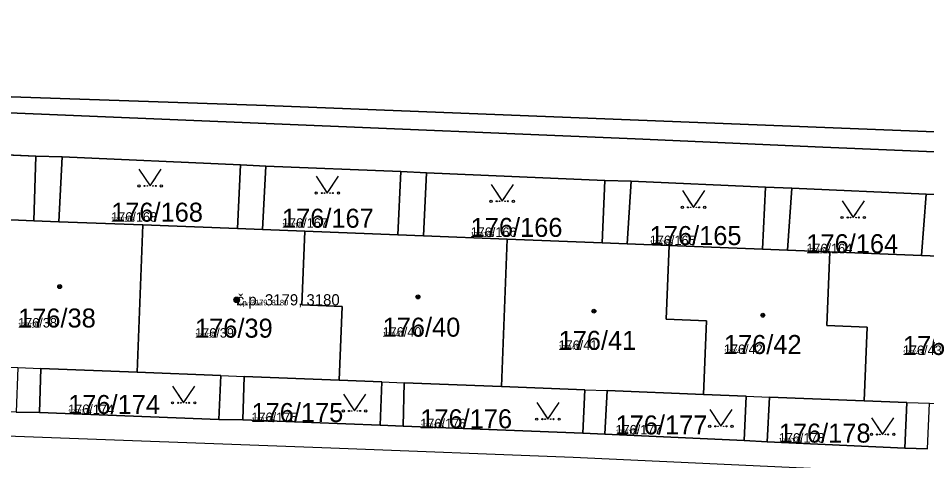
# Model space of a CAD drawing. Extents: x -759873 to -758487, y -975024 to -973516.
# Drawn here: x -759380.2 to -759298.9, y -974864.9 to -974825.3 of the extents above; entities that cross this region are included whole.
import ezdxf

# ---------------------------------------------------------------- set-up
doc = ezdxf.new("R2010")
doc.units = 0
for name, color, linetype in [('KAT_02_hranice parcel', 7, 'Continuous'), ('KAT_03_1000_st čísla parcelní', 7, 'Continuous'), ('KAT_03_1000_čísla parcelní', 7, 'Continuous'), ('KAT_03_1000_čísla popisná', 7, 'Continuous'), ('KAT_03_250_st čísla parcelní', 7, 'Continuous'), ('KAT_03_250_čísla parcelní', 7, 'Continuous'), ('KAT_03_250_čísla popisná', 7, 'Continuous'), ('KAT_03_500_st čísla parcelní', 7, 'Continuous'), ('KAT_03_500_čísla parcelní', 7, 'Continuous'), ('KAT_03_500_čísla popisná', 7, 'Continuous'), ('KAT_04_vnitřní kresba', 7, 'Continuous'), ('KAT_05_1000_značky kultur', 7, 'Continuous'), ('KAT_05_250_značky kultur', 7, 'Continuous'), ('KAT_05_500_značky kultur', 7, 'Continuous'), ('KAT_07_1000_značky budov', 7, 'Continuous'), ('KAT_07_250_značky budov', 7, 'Continuous'), ('KAT_07_500_značky budov', 7, 'Continuous'), ('KAT_14_plocha_budovy', 7, 'Continuous'), ('KAT_14_plocha_pozemek', 7, 'Continuous')]:
    doc.layers.add(name, color=color, linetype=linetype)

msp = doc.modelspace()

# ---------------------------------------------------------------- linework, layer by layer
at = {"layer": 'KAT_02_hranice parcel'}
for p, q in [((-759390.6, -974837.16), (-759378.65, -974837.7)), ((-759376.31, -974837.75), (-759378.65, -974837.7)), ((-759376.31, -974837.75), (-759360.35, -974838.46)), ((-759358.06, -974838.57), (-759360.35, -974838.46)), ((-759358.06, -974838.57), (-759345.99, -974839.06)), ((-759343.69, -974839.17), (-759345.99, -974839.06)), ((-759343.69, -974839.17), (-759327.72, -974839.85)), ((-759325.36, -974839.92), (-759327.72, -974839.85)), ((-759325.36, -974839.92), (-759313.34, -974840.46)), ((-759311, -974840.55), (-759313.34, -974840.46)), ((-759311, -974840.55), (-759298.96, -974841.08)), ((-759296.85, -974841.17), (-759298.96, -974841.08)), ((-759369.6, -974857.02), (-759369.08, -974843.84)), ((-759336.99, -974858.3), (-759336.48, -974845.12)), ((-759380.41, -974860.6), (-759378.32, -974860.64)), ((-759378.32, -974860.64), (-759362.27, -974861.24)), ((-759362.27, -974861.24), (-759360.14, -974861.28)), ((-759360.14, -974861.28), (-759347.83, -974861.77)), ((-759347.83, -974861.77), (-759345.79, -974861.85)), ((-759345.79, -974861.85), (-759329.71, -974862.47)), ((-759329.71, -974862.47), (-759327.72, -974862.56)), ((-759327.72, -974862.56), (-759315.26, -974863.12)), ((-759315.26, -974863.12), (-759313.19, -974863.24)), ((-759313.19, -974863.24), (-759300.86, -974863.82)), ((-759300.86, -974863.82), (-759298.85, -974863.88))]:
    msp.add_line(p, q, dxfattribs=at)
for points in [[(-759382.67, -974832.32), (-759358.04, -974833.14), (-759286.08, -974836), (-759287.93, -974822.96), (-759288.84, -974816.61), (-759289.72, -974807.13), (-759291.76, -974802.52), (-759298.13, -974787.72), (-759322.87, -974786.95)], [(-759281.55, -974837.72), (-759288.97, -974837.7), (-759308.21, -974836.87), (-759325.02, -974836.15), (-759358.04, -974834.77), (-759390.43, -974833.42), (-759411.31, -974832.59), (-759418.48, -974833.88), (-759427.06, -974838.9), (-759442.22, -974854.65)], [(-759378.65, -974837.7), (-759378.84, -974843.46), (-759387.18, -974843.13)], [(-759369.08, -974843.84), (-759376.59, -974843.55), (-759376.31, -974837.75)], [(-759360.35, -974838.46), (-759360.62, -974844.17), (-759369.08, -974843.84)], [(-759354.58, -974844.41), (-759358.36, -974844.26), (-759358.06, -974838.57)], [(-759345.99, -974839.06), (-759346.25, -974844.74), (-759354.58, -974844.41)], [(-759336.48, -974845.12), (-759343.97, -974844.83), (-759343.69, -974839.17)], [(-759327.72, -974839.85), (-759327.98, -974845.45), (-759336.48, -974845.12)], [(-759321.97, -974845.68), (-759325.73, -974845.54), (-759325.36, -974839.92)], [(-759313.34, -974840.46), (-759313.6, -974846.01), (-759321.97, -974845.68)], [(-759307.59, -974846.25), (-759311.37, -974846.1), (-759311, -974840.55)], [(-759298.96, -974841.08), (-759299.38, -974846.57), (-759307.59, -974846.25)], [(-759351.5, -974857.73), (-759351.24, -974851.14), (-759354.84, -974850.99), (-759354.58, -974844.41)], [(-759318.89, -974859.01), (-759318.63, -974852.41), (-759322.23, -974852.27), (-759321.97, -974845.68)], [(-759304.51, -974859.57), (-759304.25, -974852.98), (-759307.85, -974852.84), (-759307.59, -974846.25)], [(-759378.32, -974860.64), (-759378.22, -974856.68), (-759369.6, -974857.02)], [(-759369.6, -974857.02), (-759362.1, -974857.31), (-759362.27, -974861.24)], [(-759360.14, -974861.28), (-759360.02, -974857.4), (-759351.5, -974857.73)], [(-759351.5, -974857.73), (-759347.69, -974857.88), (-759347.83, -974861.77)], [(-759345.79, -974861.85), (-759345.68, -974857.96), (-759336.99, -974858.3)], [(-759336.99, -974858.3), (-759329.52, -974858.59), (-759329.71, -974862.47)], [(-759327.72, -974862.56), (-759327.52, -974858.67), (-759318.89, -974859.01)], [(-759318.89, -974859.01), (-759315.08, -974859.16), (-759315.26, -974863.12)], [(-759313.19, -974863.24), (-759313, -974859.24), (-759304.51, -974859.57)], [(-759304.51, -974859.57), (-759300.7, -974859.72), (-759300.86, -974863.82)]]:
    msp.add_lwpolyline(points, dxfattribs=at)
at = {"layer": 'KAT_03_1000_čísla popisná'}
msp.add_circle((-759360.68, -974850.54), 0.25, dxfattribs=at)
at = {"layer": 'KAT_03_250_čísla popisná'}
msp.add_circle((-759360.68, -974850.54), 0.0625, dxfattribs=at)
at = {"layer": 'KAT_03_500_čísla popisná'}
msp.add_circle((-759360.68, -974850.54), 0.125, dxfattribs=at)
at = {"layer": 'KAT_04_vnitřní kresba'}
for p, q in [((-759378.84, -974843.46), (-759376.59, -974843.55)), ((-759360.62, -974844.17), (-759358.36, -974844.26)), ((-759346.25, -974844.74), (-759343.97, -974844.83)), ((-759327.98, -974845.45), (-759325.73, -974845.54)), ((-759313.6, -974846.01), (-759311.37, -974846.1)), ((-759299.38, -974846.57), (-759297.02, -974846.66)), ((-759380.28, -974856.6), (-759378.22, -974856.68)), ((-759362.1, -974857.31), (-759360.02, -974857.4)), ((-759347.69, -974857.88), (-759345.68, -974857.96)), ((-759329.52, -974858.59), (-759327.52, -974858.67)), ((-759315.08, -974859.16), (-759313, -974859.24)), ((-759300.7, -974859.72), (-759298.66, -974859.8)), ((-759382.57, -974862.68), (-759352.26, -974863.8)), ((-759352.26, -974863.8), (-759330.55, -974864.62)), ((-759330.55, -974864.62), (-759305.43, -974865.78))]:
    msp.add_line(p, q, dxfattribs=at)
at = {"layer": 'KAT_05_1000_značky kultur'}
for points in [[(-759369.43, -974838.849), (-759368.43, -974840.35), (-759367.43, -974838.849)], [(-759353.57, -974839.489), (-759352.57, -974840.99), (-759351.57, -974839.489)], [(-759337.91, -974840.219), (-759336.91, -974841.72), (-759335.91, -974840.219)], [(-759320.79, -974840.769), (-759319.79, -974842.27), (-759318.79, -974840.769)], [(-759306.49, -974841.679), (-759305.49, -974843.18), (-759304.49, -974841.679)], [(-759366.43, -974858.259), (-759365.43, -974859.76), (-759364.43, -974858.259)], [(-759351.13, -974858.989), (-759350.13, -974860.49), (-759349.13, -974858.989)], [(-759333.82, -974859.719), (-759332.82, -974861.22), (-759331.82, -974859.719)], [(-759318.34, -974860.359), (-759317.34, -974861.86), (-759316.34, -974860.359)], [(-759303.86, -974861.089), (-759302.86, -974862.59), (-759301.86, -974861.089)]]:
    msp.add_lwpolyline(points, dxfattribs=at)
for centre in [(-759369.43, -974840.349), (-759367.43, -974840.349), (-759353.57, -974840.989), (-759351.57, -974840.989), (-759337.91, -974841.719), (-759335.91, -974841.719), (-759320.79, -974842.269), (-759318.79, -974842.269), (-759306.49, -974843.179), (-759304.49, -974843.179), (-759366.43, -974859.759), (-759364.43, -974859.759), (-759351.13, -974860.489), (-759349.13, -974860.489), (-759333.82, -974861.219), (-759331.82, -974861.219), (-759318.34, -974861.859), (-759316.34, -974861.859), (-759303.86, -974862.589), (-759301.86, -974862.589)]:
    msp.add_circle(centre, 0.1, dxfattribs=at)
at = {"layer": 'KAT_05_250_značky kultur'}
for points in [[(-759368.68, -974839.975), (-759368.43, -974840.35), (-759368.18, -974839.975)], [(-759352.82, -974840.615), (-759352.57, -974840.99), (-759352.32, -974840.615)], [(-759337.16, -974841.345), (-759336.91, -974841.72), (-759336.66, -974841.345)], [(-759320.04, -974841.895), (-759319.79, -974842.27), (-759319.54, -974841.895)], [(-759305.74, -974842.805), (-759305.49, -974843.18), (-759305.24, -974842.805)], [(-759365.68, -974859.385), (-759365.43, -974859.76), (-759365.18, -974859.385)], [(-759350.38, -974860.115), (-759350.13, -974860.49), (-759349.88, -974860.115)], [(-759333.07, -974860.845), (-759332.82, -974861.22), (-759332.57, -974860.845)], [(-759317.59, -974861.485), (-759317.34, -974861.86), (-759317.09, -974861.485)], [(-759303.11, -974862.215), (-759302.86, -974862.59), (-759302.61, -974862.215)]]:
    msp.add_lwpolyline(points, dxfattribs=at)
for centre in [(-759368.68, -974840.35), (-759368.18, -974840.35), (-759352.82, -974840.99), (-759352.32, -974840.99), (-759337.16, -974841.72), (-759336.66, -974841.72), (-759320.04, -974842.27), (-759319.54, -974842.27), (-759305.74, -974843.18), (-759305.24, -974843.18), (-759365.68, -974859.76), (-759365.18, -974859.76), (-759350.38, -974860.49), (-759349.88, -974860.49), (-759333.07, -974861.22), (-759332.57, -974861.22), (-759317.59, -974861.86), (-759317.09, -974861.86), (-759303.11, -974862.59), (-759302.61, -974862.59)]:
    msp.add_circle(centre, 0.025, dxfattribs=at)
at = {"layer": 'KAT_05_500_značky kultur'}
for points in [[(-759368.93, -974839.6), (-759368.43, -974840.35), (-759367.93, -974839.6)], [(-759353.07, -974840.24), (-759352.57, -974840.99), (-759352.07, -974840.24)], [(-759337.41, -974840.97), (-759336.91, -974841.72), (-759336.41, -974840.97)], [(-759320.29, -974841.52), (-759319.79, -974842.27), (-759319.29, -974841.52)], [(-759305.99, -974842.429), (-759305.49, -974843.18), (-759304.99, -974842.429)], [(-759365.93, -974859.01), (-759365.43, -974859.76), (-759364.93, -974859.01)], [(-759350.63, -974859.74), (-759350.13, -974860.49), (-759349.63, -974859.74)], [(-759333.32, -974860.47), (-759332.82, -974861.22), (-759332.32, -974860.47)], [(-759317.84, -974861.11), (-759317.34, -974861.86), (-759316.84, -974861.11)], [(-759303.36, -974861.84), (-759302.86, -974862.59), (-759302.36, -974861.84)]]:
    msp.add_lwpolyline(points, dxfattribs=at)
for centre in [(-759368.93, -974840.35), (-759367.93, -974840.35), (-759353.07, -974840.99), (-759352.07, -974840.99), (-759337.41, -974841.72), (-759336.41, -974841.72), (-759320.29, -974842.27), (-759319.29, -974842.27), (-759305.99, -974843.18), (-759304.99, -974843.18), (-759365.93, -974859.76), (-759364.93, -974859.76), (-759350.63, -974860.49), (-759349.63, -974860.49), (-759333.32, -974861.22), (-759332.32, -974861.22), (-759317.84, -974861.86), (-759316.84, -974861.86), (-759303.36, -974862.59), (-759302.36, -974862.59)]:
    msp.add_circle(centre, 0.05, dxfattribs=at)
at = {"layer": 'KAT_07_1000_značky budov'}
for centre in [(-759376.527, -974849.359), (-759360.687, -974850.539), (-759344.457, -974850.279), (-759328.707, -974851.559), (-759313.587, -974851.919)]:
    msp.add_circle(centre, 0.175, dxfattribs=at)
at = {"layer": 'KAT_07_250_značky budov'}
for centre in [(-759376.522, -974849.36), (-759360.682, -974850.54), (-759344.452, -974850.28), (-759328.702, -974851.56), (-759313.582, -974851.92)]:
    msp.add_circle(centre, 0.0437, dxfattribs=at)
at = {"layer": 'KAT_07_500_značky budov'}
for centre in [(-759376.523, -974849.36), (-759360.683, -974850.54), (-759344.453, -974850.28), (-759328.703, -974851.56), (-759313.583, -974851.92)]:
    msp.add_circle(centre, 0.0875, dxfattribs=at)
at = {"layer": 'KAT_14_plocha_budovy'}
for points in [[(-759369.6, -974857.02), (-759369.08, -974843.84), (-759376.59, -974843.55), (-759378.84, -974843.46), (-759387.18, -974843.13), (-759390.57, -974843), (-759393.24, -974842.9), (-759401.56, -974842.57), (-759405.36, -974842.42), (-759407.59, -974842.34), (-759416.17, -974842), (-759416.68, -974855.18), (-759409.09, -974855.48), (-759407.03, -974855.56), (-759398.48, -974855.89), (-759394.62, -974856.04), (-759392.65, -974856.12), (-759384.11, -974856.45), (-759380.28, -974856.6), (-759378.22, -974856.68)], [(-759369.6, -974857.02), (-759362.1, -974857.31), (-759360.02, -974857.4), (-759351.5, -974857.73), (-759347.69, -974857.88), (-759345.68, -974857.96), (-759336.99, -974858.3), (-759336.48, -974845.12), (-759343.97, -974844.83), (-759346.25, -974844.74), (-759354.58, -974844.41), (-759358.36, -974844.26), (-759360.62, -974844.17), (-759369.08, -974843.84)], [(-759304.51, -974859.57), (-759300.7, -974859.72), (-759298.66, -974859.8), (-759289.9, -974860.14), (-759289.38, -974846.96), (-759297.02, -974846.66), (-759299.38, -974846.57), (-759307.59, -974846.25), (-759311.37, -974846.1), (-759313.6, -974846.01), (-759321.97, -974845.68), (-759325.73, -974845.54), (-759327.98, -974845.45), (-759336.48, -974845.12), (-759336.99, -974858.3), (-759329.52, -974858.59), (-759327.52, -974858.67), (-759318.89, -974859.01), (-759315.08, -974859.16), (-759313, -974859.24)]]:
    msp.add_lwpolyline(points, close=True, dxfattribs=at)
at = {"layer": 'KAT_14_plocha_pozemek'}
for points in [[(-759286.08, -974836), (-759358.04, -974833.14), (-759382.67, -974832.32), (-759413.9, -974831.28), (-759416.69, -974831.27), (-759419.67, -974831.59), (-759422.46, -974832.5), (-759424.85, -974834.26), (-759443.37, -974853.62), (-759442.22, -974854.65), (-759427.06, -974838.9), (-759418.48, -974833.88), (-759411.31, -974832.59), (-759390.43, -974833.42), (-759358.04, -974834.77), (-759325.02, -974836.15), (-759308.21, -974836.87), (-759288.97, -974837.7)], [(-759382.67, -974832.32), (-759358.04, -974833.14), (-759286.08, -974836)], [(-759288.97, -974837.7), (-759308.21, -974836.87), (-759325.02, -974836.15), (-759358.04, -974834.77), (-759390.43, -974833.42)], [(-759390.6, -974837.16), (-759378.65, -974837.7), (-759376.31, -974837.75), (-759360.35, -974838.46), (-759358.06, -974838.57), (-759345.99, -974839.06), (-759343.69, -974839.17), (-759327.72, -974839.85), (-759325.36, -974839.92), (-759313.34, -974840.46), (-759311, -974840.55), (-759298.96, -974841.08), (-759296.85, -974841.17)], [(-759378.32, -974860.64), (-759380.41, -974860.6), (-759392.56, -974860.11), (-759394.77, -974860.08), (-759407.08, -974859.58), (-759409.14, -974859.51), (-759420.83, -974858.95), (-759422.15, -974858.9), (-759440.79, -974858.2), (-759441.93, -974860.34), (-759434.47, -974860.67), (-759434.72, -974865.02)], [(-759298.85, -974863.88), (-759300.86, -974863.82), (-759313.19, -974863.24), (-759315.26, -974863.12), (-759327.72, -974862.56), (-759329.71, -974862.47), (-759345.79, -974861.85), (-759347.83, -974861.77), (-759360.14, -974861.28), (-759362.27, -974861.24), (-759378.32, -974860.64)]]:
    msp.add_lwpolyline(points, dxfattribs=at)
for points in [[(-759390.6, -974837.16), (-759390.57, -974843), (-759387.18, -974843.13), (-759378.84, -974843.46), (-759378.65, -974837.7)], [(-759376.31, -974837.75), (-759378.65, -974837.7), (-759378.84, -974843.46), (-759387.18, -974843.13), (-759387.44, -974849.72), (-759383.85, -974849.86), (-759384.11, -974856.45), (-759380.28, -974856.6), (-759380.41, -974860.6), (-759378.32, -974860.64), (-759378.22, -974856.68), (-759369.6, -974857.02), (-759369.08, -974843.84), (-759376.59, -974843.55)], [(-759376.31, -974837.75), (-759376.59, -974843.55), (-759369.08, -974843.84), (-759360.62, -974844.17), (-759360.35, -974838.46)], [(-759362.1, -974857.31), (-759362.27, -974861.24), (-759360.14, -974861.28), (-759360.02, -974857.4), (-759351.5, -974857.73), (-759351.24, -974851.14), (-759354.84, -974850.99), (-759354.58, -974844.41), (-759358.36, -974844.26), (-759358.06, -974838.57), (-759360.35, -974838.46), (-759360.62, -974844.17), (-759369.08, -974843.84), (-759369.6, -974857.02)], [(-759358.06, -974838.57), (-759358.36, -974844.26), (-759354.58, -974844.41), (-759346.25, -974844.74), (-759345.99, -974839.06)], [(-759345.68, -974857.96), (-759336.99, -974858.3), (-759336.48, -974845.12), (-759343.97, -974844.83), (-759343.69, -974839.17), (-759345.99, -974839.06), (-759346.25, -974844.74), (-759354.58, -974844.41), (-759354.84, -974850.99), (-759351.24, -974851.14), (-759351.5, -974857.73), (-759347.69, -974857.88), (-759347.83, -974861.77), (-759345.79, -974861.85)], [(-759343.69, -974839.17), (-759343.97, -974844.83), (-759336.48, -974845.12), (-759327.98, -974845.45), (-759327.72, -974839.85)], [(-759327.72, -974839.85), (-759327.98, -974845.45), (-759336.48, -974845.12), (-759336.99, -974858.3), (-759329.52, -974858.59), (-759329.71, -974862.47), (-759327.72, -974862.56), (-759327.52, -974858.67), (-759318.89, -974859.01), (-759318.63, -974852.41), (-759322.23, -974852.27), (-759321.97, -974845.68), (-759325.73, -974845.54), (-759325.36, -974839.92)], [(-759325.36, -974839.92), (-759325.73, -974845.54), (-759321.97, -974845.68), (-759313.6, -974846.01), (-759313.34, -974840.46)], [(-759313.34, -974840.46), (-759313.6, -974846.01), (-759321.97, -974845.68), (-759322.23, -974852.27), (-759318.63, -974852.41), (-759318.89, -974859.01), (-759315.08, -974859.16), (-759315.26, -974863.12), (-759313.19, -974863.24), (-759313, -974859.24), (-759304.51, -974859.57), (-759304.25, -974852.98), (-759307.85, -974852.84), (-759307.59, -974846.25), (-759311.37, -974846.1), (-759311, -974840.55)], [(-759311, -974840.55), (-759311.37, -974846.1), (-759307.59, -974846.25), (-759299.38, -974846.57), (-759298.96, -974841.08)], [(-759296.85, -974841.17), (-759298.96, -974841.08), (-759299.38, -974846.57), (-759307.59, -974846.25), (-759307.85, -974852.84), (-759304.25, -974852.98), (-759304.51, -974859.57), (-759300.7, -974859.72), (-759300.86, -974863.82), (-759298.85, -974863.88), (-759298.66, -974859.8), (-759289.9, -974860.14), (-759289.38, -974846.96), (-759297.02, -974846.66)], [(-759362.27, -974861.24), (-759362.1, -974857.31), (-759369.6, -974857.02), (-759378.22, -974856.68), (-759378.32, -974860.64)], [(-759347.83, -974861.77), (-759347.69, -974857.88), (-759351.5, -974857.73), (-759360.02, -974857.4), (-759360.14, -974861.28)], [(-759329.71, -974862.47), (-759329.52, -974858.59), (-759336.99, -974858.3), (-759345.68, -974857.96), (-759345.79, -974861.85)], [(-759315.26, -974863.12), (-759315.08, -974859.16), (-759318.89, -974859.01), (-759327.52, -974858.67), (-759327.72, -974862.56)], [(-759300.86, -974863.82), (-759300.7, -974859.72), (-759304.51, -974859.57), (-759313, -974859.24), (-759313.19, -974863.24)]]:
    msp.add_lwpolyline(points, close=True, dxfattribs=at)

# ---------------------------------------------------------------- texts
at = {"layer": 'KAT_03_1000_st čísla parcelní'}
for s, p in [('176/38', (-759380.25, -974853.02)), ('176/39', (-759364.41, -974853.929)), ('176/40', (-759347.62, -974853.84)), ('176/41', (-759331.87, -974855.02)), ('176/42', (-759317.07, -974855.39)), ('176/43', (-759301.05, -974855.48))]:
    msp.add_text(s, height=1.7, dxfattribs=at).set_placement(p)
at = {"layer": 'KAT_03_1000_čísla parcelní'}
for s, p in [('176/168', (-759371.92, -974843.549)), ('176/167', (-759356.63, -974844.09)), ('176/166', (-759339.74, -974844.91)), ('176/165', (-759323.71, -974845.64)), ('176/164', (-759309.69, -974846.37)), ('176/174', (-759375.77, -974860.76)), ('176/175', (-759359.36, -974861.48)), ('176/176', (-759344.25, -974862.039)), ('176/177', (-759326.77, -974862.59)), ('176/178', (-759312.16, -974863.32))]:
    msp.add_text(s, height=1.7, dxfattribs=at).set_placement(p)
at = {"layer": 'KAT_03_1000_čísla popisná'}
msp.add_text('č.p. 3179, 3180', height=1, dxfattribs=at).set_placement((-759360.68, -974851.04))
at = {"layer": 'KAT_03_250_st čísla parcelní'}
for s, p in [('176/38', (-759380.25, -974853.02)), ('176/39', (-759364.41, -974853.929)), ('176/40', (-759347.62, -974853.84)), ('176/41', (-759331.87, -974855.02)), ('176/42', (-759317.07, -974855.39)), ('176/43', (-759301.05, -974855.48))]:
    msp.add_text(s, height=0.425, dxfattribs=at).set_placement(p)
at = {"layer": 'KAT_03_250_čísla parcelní'}
for s, p in [('176/168', (-759371.92, -974843.549)), ('176/167', (-759356.63, -974844.09)), ('176/166', (-759339.74, -974844.91)), ('176/165', (-759323.71, -974845.64)), ('176/164', (-759309.69, -974846.37)), ('176/174', (-759375.77, -974860.76)), ('176/175', (-759359.36, -974861.48)), ('176/176', (-759344.25, -974862.039)), ('176/177', (-759326.77, -974862.59)), ('176/178', (-759312.16, -974863.32))]:
    msp.add_text(s, height=0.425, dxfattribs=at).set_placement(p)
at = {"layer": 'KAT_03_250_čísla popisná'}
msp.add_text('č.p. 3179, 3180', height=0.25, dxfattribs=at).set_placement((-759360.68, -974851.04))
at = {"layer": 'KAT_03_500_st čísla parcelní'}
for s, p in [('176/38', (-759380.25, -974853.02)), ('176/39', (-759364.41, -974853.929)), ('176/40', (-759347.62, -974853.84)), ('176/41', (-759331.87, -974855.02)), ('176/42', (-759317.07, -974855.39)), ('176/43', (-759301.05, -974855.48))]:
    msp.add_text(s, height=0.85, dxfattribs=at).set_placement(p)
at = {"layer": 'KAT_03_500_čísla parcelní'}
for s, p in [('176/168', (-759371.92, -974843.549)), ('176/167', (-759356.63, -974844.09)), ('176/166', (-759339.74, -974844.91)), ('176/165', (-759323.71, -974845.64)), ('176/164', (-759309.69, -974846.37)), ('176/174', (-759375.77, -974860.76)), ('176/175', (-759359.36, -974861.48)), ('176/176', (-759344.25, -974862.039)), ('176/177', (-759326.77, -974862.59)), ('176/178', (-759312.16, -974863.32))]:
    msp.add_text(s, height=0.85, dxfattribs=at).set_placement(p)
at = {"layer": 'KAT_03_500_čísla popisná'}
msp.add_text('č.p. 3179, 3180', height=0.5, dxfattribs=at).set_placement((-759360.68, -974851.04))

doc.saveas('drawing.dxf')
